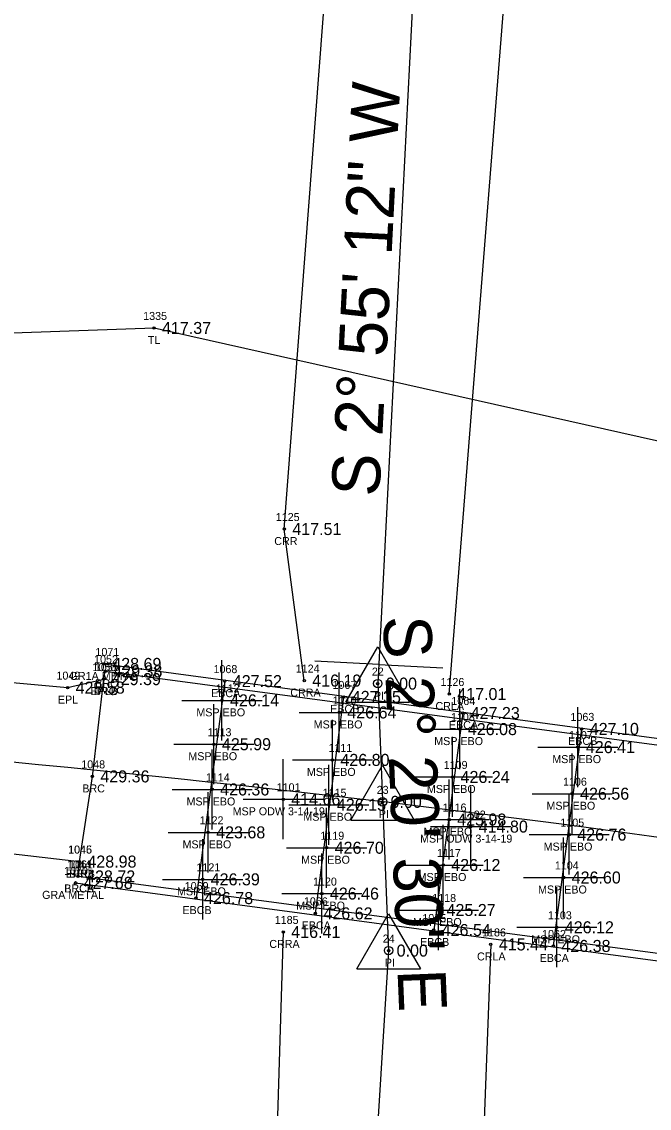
# Model space of a CAD drawing. Extents: x 1611114 to 1617038, y 769445 to 772083.
# Drawn here: x 1613882.1 to 1613960.4, y 771305 to 771440.8 of the extents above; entities that cross this region are included whole.
import ezdxf

# ---------------------------------------------------------------- set-up
doc = ezdxf.new("R2010")
doc.units = 0
for name, color, linetype in [('Default', 7, 'Continuous'), ('RD_EX_Bridge', 7, 'Continuous'), ('RD_EX_Bridge_txCode', 7, 'Continuous'), ('RD_EX_GuardRail', 7, 'Continuous'), ('RD_EX_GuardRail_txCode', 7, 'Continuous'), ('RD_EX_H2O', 7, 'Continuous'), ('RD_EX_H2O_txCode', 7, 'Continuous'), ('RD_EX_Road', 7, 'Continuous'), ('RD_EX_Road_txCode', 7, 'Continuous'), ('RD_EX_TX_Bridge_ELEV', 7, 'Continuous'), ('RD_EX_TX_GuardRail_ELEV', 7, 'Continuous'), ('RD_EX_TX_H2O_ELEV', 7, 'Continuous'), ('RD_EX_TX_Misc_ELEV', 7, 'Continuous'), ('RD_EX_TX_Road_ELEV', 7, 'Continuous'), ('RD_EX_TX_VEG_ELEV', 7, 'Continuous'), ('RD_EX_VEG', 7, 'Continuous'), ('RD_EX_VEG_txCode', 7, 'Continuous'), ('RD_HC_Cl', 7, 'Continuous'), ('RD_HC_Data', 7, 'Continuous'), ('RD_HC_Data_Tic', 7, 'Continuous'), ('RD_HC_Survey_ELEV', 7, 'Continuous'), ('RD_HC_txCode', 7, 'Continuous'), ('RD_SMD_Locator', 7, 'Continuous')]:
    doc.layers.add(name, color=color, linetype=linetype)

msp = doc.modelspace()

# ---------------------------------------------------------------- linework, layer by layer
at = {"layer": 'Default'}
for p, q in [((1613931.57, 771457.25), (1613926.51, 771358.07)), ((1613926.51, 771358.07), (1613927.87, 771324.72)), ((1613927.87, 771324.72), (1613922.18, 771233.88))]:
    msp.add_line(p, q, dxfattribs=at)
msp.add_arc((1613700.84, 769446.93), 1909.82, 80.96676, 95.06271, dxfattribs=at)
msp.add_arc((1613700.84, 769446.93), 1909.82, 80.96676, 95.06271, dxfattribs=at)
at = {"layer": 'RD_EX_Bridge'}
for p, q in [((1613907.06, 771350.98), (1613907.06, 771360.98)), ((1613921.71, 771349.47), (1613921.71, 771359.47)), ((1613907.41, 771358.38), (1613903.82, 771331.28)), ((1613936.76, 771347.39), (1613936.76, 771357.39)), ((1613902.06, 771355.98), (1613912.06, 771355.98)), ((1613906.05, 771345.5), (1613906.05, 771355.5)), ((1613918.73, 771329.37), (1613922.27, 771356.41)), ((1613916.71, 771354.47), (1613926.71, 771354.47)), ((1613937.12, 771354.4), (1613933.5, 771327.29)), ((1613951.5, 771345.14), (1613951.5, 771355.14)), ((1613920.85, 771343.54), (1613920.85, 771353.54)), ((1613931.76, 771352.39), (1613941.76, 771352.39)), ((1613935.85, 771341.41), (1613935.85, 771351.41)), ((1613948.45, 771325.3), (1613951.99, 771352.41)), ((1613901.05, 771350.5), (1613911.05, 771350.5)), ((1613946.5, 771350.14), (1613956.5, 771350.14)), ((1613905.83, 771339.85), (1613905.83, 771349.85)), ((1613950.78, 771339.32), (1613950.78, 771349.32)), ((1613915.85, 771348.54), (1613925.85, 771348.54)), ((1613920.41, 771337.94), (1613920.41, 771347.94)), ((1613930.85, 771346.41), (1613940.85, 771346.41)), ((1613935.43, 771336.09), (1613935.43, 771346.09)), ((1613900.83, 771344.85), (1613910.83, 771344.85)), ((1613905.33, 771334.49), (1613905.33, 771344.49)), ((1613945.78, 771344.32), (1613955.78, 771344.32)), ((1613950.43, 771334.21), (1613950.43, 771344.21)), ((1613915.41, 771342.94), (1613925.41, 771342.94)), ((1613920.13, 771332.57), (1613920.13, 771342.57)), ((1613930.43, 771341.09), (1613940.43, 771341.09)), ((1613900.33, 771339.49), (1613910.33, 771339.49)), ((1613934.69, 771330.41), (1613934.69, 771340.41)), ((1613945.43, 771339.21), (1613955.43, 771339.21)), ((1613904.65, 771328.62), (1613904.65, 771338.62)), ((1613949.73, 771328.85), (1613949.73, 771338.85)), ((1613915.13, 771337.57), (1613925.13, 771337.57)), ((1613919.53, 771326.84), (1613919.53, 771336.84)), ((1613929.69, 771335.41), (1613939.69, 771335.41)), ((1613934.1, 771324.79), (1613934.1, 771334.79)), ((1613944.73, 771333.85), (1613954.73, 771333.85)), ((1613899.65, 771333.62), (1613909.65, 771333.62)), ((1613948.87, 771322.63), (1613948.87, 771332.63)), ((1613914.53, 771331.84), (1613924.53, 771331.84)), ((1613929.1, 771329.79), (1613939.1, 771329.79)), ((1613943.87, 771327.63), (1613953.87, 771327.63))]:
    msp.add_line(p, q, dxfattribs=at)
msp.add_lwpolyline([(1613889.09, 771333.98), (1613889.25, 771335.84), (1613890.87, 771346.48), (1613892.3, 771358.63), (1613892.48, 771359.61), (1613966.64, 771349.7), (1613966.21, 771346.72), (1613965.11, 771336.88), (1613963.41, 771324.71), (1613963.37, 771324.1), (1613889.09, 771333.98)], dxfattribs=at)
for centre in [(1613907.06, 771355.98), (1613921.71, 771354.47), (1613936.76, 771352.39), (1613906.05, 771350.5), (1613951.5, 771350.14), (1613920.85, 771348.54), (1613935.85, 771346.41), (1613905.83, 771344.85), (1613950.78, 771344.32), (1613920.41, 771342.94), (1613935.43, 771341.09), (1613905.33, 771339.49), (1613950.43, 771339.21), (1613920.13, 771337.57), (1613934.69, 771335.41), (1613904.65, 771333.62), (1613949.73, 771333.85), (1613919.53, 771331.84), (1613934.1, 771329.79), (1613948.87, 771327.63)]:
    msp.add_circle(centre, 0.15, dxfattribs=at)
at = {"layer": 'RD_EX_GuardRail'}
for p, q in [((1613892.36, 771360.53), (1613966.88, 771350.5)), ((1613888.77, 771333.18), (1613963.37, 771323.19))]:
    msp.add_line(p, q, dxfattribs=at)
at = {"layer": 'RD_EX_H2O'}
for p, q in [((1613914.71, 771338.62), (1613914.71, 771348.62)), ((1613938.12, 771335.21), (1613938.12, 771345.21)), ((1613909.71, 771343.62), (1613919.71, 771343.62)), ((1613933.12, 771340.21), (1613943.12, 771340.21))]:
    msp.add_line(p, q, dxfattribs=at)
for points in [[(1613935.44, 771356.77), (1613943.27, 771455.38), (1613930.01, 771555.13), (1613904.31, 771653.52), (1613890.61, 771671.71), (1613879.59, 771707.51), (1613867.74, 771752.9), (1613852.65, 771773.53), (1613849.08, 771793.99), (1613835.96, 771848.52)], [(1613917.33, 771358.45), (1613914.84, 771377.38), (1613920.97, 771458.1), (1613902.34, 771553.43), (1613877.06, 771642.7), (1613869.36, 771660.93), (1613852.51, 771699.26), (1613841.87, 771743.26), (1613831.92, 771763.8), (1613826.06, 771789.11), (1613812.2, 771844.94)], [(1613914.71, 771327.05), (1613912.94, 771270.2), (1613909.29, 771229.14), (1613936.32, 771173.24), (1613961.59, 771155.78), (1613976.99, 771153.11), (1613987.89, 771138.66), (1614016.07, 771061.15), (1614064.07, 770971.34), (1614114.62, 770881.02)], [(1613940.63, 771325.49), (1613938.42, 771267.33), (1613934.3, 771235.92), (1613956.7, 771194.52), (1613973.34, 771185.91), (1613987.6, 771179.19), (1614011.07, 771155.33), (1614038.76, 771071.93), (1614097.41, 770977.46), (1614139.24, 770893.98)]]:
    msp.add_lwpolyline(points, dxfattribs=at)
for centre in [(1613914.71, 771343.62), (1613938.12, 771340.21)]:
    msp.add_circle(centre, 0.15, dxfattribs=at)
at = {"layer": 'RD_EX_Road'}
for points in [[(1613192.48, 771329.15), (1613292.05, 771338.23), (1613391, 771348.45), (1613492.61, 771357.17), (1613541.86, 771361.21), (1613591.56, 771364.71), (1613642.92, 771366.4), (1613692.81, 771367.35), (1613742.66, 771367.02), (1613792.19, 771365.04), (1613843.32, 771361.63), (1613887.78, 771357.57), (1613892.3, 771358.63)], [(1613194.6, 771309.27), (1613294.55, 771318.15), (1613393.75, 771328.31), (1613493.74, 771336.74), (1613544.27, 771340.57), (1613593.48, 771343.76), (1613642.77, 771345.54), (1613692.58, 771346.11), (1613741.71, 771345.82), (1613791.79, 771344.79), (1613840.79, 771341.46), (1613889.25, 771335.84)]]:
    msp.add_lwpolyline(points, dxfattribs=at)
at = {"layer": 'RD_EX_VEG'}
msp.add_lwpolyline([(1613190.16, 771350.86), (1613289.21, 771359.12), (1613387.94, 771369.51), (1613489.82, 771379.95), (1613503.78, 771396.75), (1613539.01, 771398.99), (1613588.71, 771402.91), (1613642.02, 771405.83), (1613690.35, 771406.29), (1613743.43, 771406.09), (1613794.76, 771402.87), (1613849.1, 771400.75), (1613898.57, 771402.5), (1614071.38, 771363.76), (1614171, 771346.54), (1614270.56, 771328.42), (1614365.98, 771308.81), (1614467.36, 771290.78), (1614565.75, 771274.12), (1614666.78, 771259.85)], dxfattribs=at)
at = {"layer": 'RD_HC_Cl'}
for p, q in [((1613931.57, 771457.25), (1613926.51, 771358.07)), ((1613926.51, 771358.07), (1613927.87, 771324.72)), ((1613927.87, 771324.72), (1613922.18, 771233.88))]:
    msp.add_line(p, q, dxfattribs=at)
msp.add_arc((1613700.84, 769446.93), 1909.82, 80.96676, 95.06271, dxfattribs=at)
at = {"layer": 'RD_HC_Data'}
for p, q in [((1613922.54, 771355.77), (1613926.51, 771362.65)), ((1613926.51, 771362.65), (1613930.48, 771355.77)), ((1613922.54, 771355.77), (1613930.48, 771355.77)), ((1613923.14, 771341.01), (1613927.11, 771347.89)), ((1613927.11, 771347.89), (1613931.08, 771341.01)), ((1613923.14, 771341.01), (1613931.08, 771341.01)), ((1613923.9, 771322.43), (1613927.87, 771329.31)), ((1613927.87, 771329.31), (1613931.84, 771322.43)), ((1613923.9, 771322.43), (1613931.84, 771322.43))]:
    msp.add_line(p, q, dxfattribs=at)
for centre in [(1613926.51, 771358.07), (1613927.11, 771343.3), (1613927.87, 771324.72)]:
    msp.add_circle(centre, 0.529, dxfattribs=at)
at = {"layer": 'RD_HC_Data_Tic'}
for q in [(1613918.64, 771360.88), (1613934.62, 771360.06)]:
    msp.add_line((1613926.63, 771360.47), q, dxfattribs=at)
at = {"layer": 'RD_SMD_Locator'}
for centre in [(1613898.57, 771402.5), (1613914.84, 771377.38), (1613892.36, 771360.53), (1613892.48, 771359.61), (1613892.3, 771358.63), (1613892.3, 771358.63), (1613907.41, 771358.38), (1613917.33, 771358.45), (1613926.51, 771358.07), (1613887.78, 771357.57), (1613935.44, 771356.77), (1613922.27, 771356.41), (1613937.12, 771354.4), (1613951.99, 771352.41), (1613890.87, 771346.48), (1613927.11, 771343.3), (1613889.25, 771335.84), (1613889.25, 771335.84), (1613889.09, 771333.98), (1613889.09, 771333.98), (1613888.77, 771333.18), (1613903.82, 771331.28), (1613918.73, 771329.37), (1613914.71, 771327.05), (1613933.5, 771327.29), (1613940.63, 771325.49), (1613927.87, 771324.72), (1613948.45, 771325.3)]:
    msp.add_circle(centre, 0.15, dxfattribs=at)

# ---------------------------------------------------------------- texts
at = {"layer": 'RD_EX_Bridge_txCode'}
for s, p in [('1052', (1613891.09, 771360.61)), ('1051', (1613891.2, 771359.63)), ('1068', (1613906, 771359.38)), ('BRC', (1613891.23, 771357.61)), ('1067', (1613920.86, 771357.41)), ('BRC', (1613891.05, 771356.63)), ('EBCA', (1613905.7, 771356.38)), ('1112', (1613906.28, 771356.98)), ('EBCB', (1613920.57, 771354.41)), ('1110', (1613920.89, 771355.47)), ('1064', (1613935.71, 771355.4)), ('MSP EBO', (1613903.86, 771353.98)), ('1108', (1613935.66, 771353.39)), ('1063', (1613950.58, 771353.41)), ('MSP EBO', (1613918.51, 771352.47)), ('EBCA', (1613935.4, 771352.4)), ('1113', (1613905.27, 771351.5)), ('MSP EBO', (1613933.57, 771350.39)), ('EBCB', (1613950.29, 771350.41)), ('1107', (1613950.4, 771351.14)), ('1111', (1613920.36, 771349.54)), ('MSP EBO', (1613902.86, 771348.5)), ('MSP EBO', (1613948.31, 771348.14)), ('1048', (1613889.49, 771347.48)), ('MSP EBO', (1613917.66, 771346.54)), ('1109', (1613934.75, 771347.41)), ('1114', (1613905.05, 771345.85)), ('1106', (1613949.65, 771345.32)), ('BRC', (1613889.62, 771344.48)), ('1115', (1613919.63, 771343.94)), ('MSP EBO', (1613932.65, 771344.41)), ('MSP EBO', (1613902.63, 771342.85)), ('MSP EBO', (1613947.58, 771342.32)), ('MSP EBO', (1613917.22, 771340.94)), ('1116', (1613934.62, 771342.09)), ('1122', (1613904.27, 771340.49)), ('1105', (1613949.32, 771340.21)), ('1119', (1613919.35, 771338.57)), ('MSP EBO', (1613932.23, 771339.09)), ('1045', (1613887.86, 771336.84)), ('MSP EBO', (1613902.13, 771337.49)), ('MSP EBO', (1613947.23, 771337.21)), ('MSP EBO', (1613916.94, 771335.57)), ('1117', (1613933.91, 771336.41)), ('1044', (1613887.71, 771334.98)), ('1061', (1613887.97, 771334.98)), ('1121', (1613903.87, 771334.62)), ('1104', (1613948.63, 771334.85)), ('BRC', (1613887.99, 771333.84)), ('1120', (1613918.43, 771332.84)), ('MSP EBO', (1613931.49, 771333.41)), ('BRCA', (1613887.35, 771331.98)), ('BRCB', (1613887.37, 771331.98)), ('MSP EBO', (1613901.45, 771331.62)), ('1069', (1613902.41, 771332.28)), ('MSP EBO', (1613946.53, 771331.85)), ('1066', (1613917.29, 771330.37)), ('1118', (1613933.32, 771330.79)), ('EBCB', (1613902.12, 771329.28)), ('MSP EBO', (1613916.33, 771329.84)), ('1103', (1613947.77, 771328.63)), ('EBCA', (1613917.01, 771327.37)), ('MSP EBO', (1613930.91, 771327.79)), ('1065', (1613932.09, 771328.29)), ('1062', (1613947.04, 771326.3)), ('EBCB', (1613931.8, 771325.29)), ('MSP EBO', (1613945.68, 771325.63)), ('EBCA', (1613946.73, 771323.3))]:
    msp.add_text(s, height=1, dxfattribs=at).set_placement(p)
at = {"layer": 'RD_EX_GuardRail_txCode'}
for s, p in [('1071', (1613891.26, 771361.53)), ('GR1A METAL', (1613888.03, 771358.53)), ('1070', (1613887.34, 771334.18)), ('GRA METAL', (1613884.6, 771331.18))]:
    msp.add_text(s, height=1, dxfattribs=at).set_placement(p)
at = {"layer": 'RD_EX_H2O_txCode'}
for s, p in [('1125', (1613913.78, 771378.38)), ('CRR', (1613913.59, 771375.38)), ('1124', (1613916.27, 771359.45)), ('1126', (1613934.35, 771357.77)), ('CRRA', (1613915.59, 771356.45)), ('CRLA', (1613933.72, 771354.77)), ('1101', (1613913.89, 771344.62)), ('MSP ODW 3-14-19', (1613908.39, 771341.62)), ('1102', (1613937.02, 771341.21)), ('MSP ODW 3-14-19', (1613931.8, 771338.21)), ('1185', (1613913.65, 771328.05)), ('1186', (1613939.54, 771326.49)), ('CRRA', (1613912.97, 771325.05)), ('CRLA', (1613938.91, 771323.49))]:
    msp.add_text(s, height=1, dxfattribs=at).set_placement(p)
at = {"layer": 'RD_EX_Road_txCode'}
for s, p in [('1049', (1613886.39, 771358.57)), ('1050', (1613890.88, 771359.63)), ('EPLB', (1613890.63, 771356.63)), ('EPL', (1613886.57, 771355.57)), ('1046', (1613887.84, 771336.84)), ('EPRB', (1613887.54, 771333.84))]:
    msp.add_text(s, height=1, dxfattribs=at).set_placement(p)
at = {"layer": 'RD_EX_TX_Bridge_ELEV'}
for s, p in [('429.38', (1613893.48, 771358.86)), ('429.39', (1613893.3, 771357.88)), ('427.52', (1613908.41, 771357.63)), ('427.35', (1613923.27, 771355.66)), ('427.23', (1613938.12, 771353.65)), ('427.10', (1613952.99, 771351.66)), ('429.36', (1613891.87, 771345.73)), ('428.98', (1613890.25, 771335.09)), ('428.72', (1613890.09, 771333.23)), ('428.72', (1613890.09, 771333.23)), ('426.78', (1613904.82, 771330.53)), ('426.62', (1613919.73, 771328.62)), ('426.54', (1613934.5, 771326.54)), ('426.38', (1613949.45, 771324.55))]:
    msp.add_text(s, height=1.5, dxfattribs=at).set_placement(p)
at = {"layer": 'RD_EX_TX_GuardRail_ELEV'}
for s, p in [('428.69', (1613893.36, 771359.78)), ('427.68', (1613889.77, 771332.43))]:
    msp.add_text(s, height=1.5, dxfattribs=at).set_placement(p)
at = {"layer": 'RD_EX_TX_H2O_ELEV'}
for s, p in [('417.51', (1613915.84, 771376.63)), ('416.19', (1613918.33, 771357.7)), ('417.01', (1613936.44, 771356.02)), ('416.41', (1613915.71, 771326.3)), ('415.44', (1613941.63, 771324.74))]:
    msp.add_text(s, height=1.5, dxfattribs=at).set_placement(p)
at = {"layer": 'RD_EX_TX_Misc_ELEV'}
for s, p in [('426.14', (1613908.06, 771355.23)), ('426.64', (1613922.71, 771353.72)), ('426.08', (1613937.76, 771351.64)), ('425.99', (1613907.05, 771349.75)), ('426.41', (1613952.5, 771349.39)), ('426.80', (1613921.85, 771347.79)), ('426.24', (1613936.85, 771345.66)), ('426.36', (1613906.83, 771344.1)), ('426.56', (1613951.78, 771343.57)), ('414.66', (1613915.71, 771342.87)), ('426.15', (1613921.41, 771342.19)), ('425.98', (1613936.43, 771340.34)), ('414.80', (1613939.12, 771339.46)), ('423.68', (1613906.33, 771338.74)), ('426.76', (1613951.43, 771338.46)), ('426.70', (1613921.13, 771336.82)), ('426.12', (1613935.69, 771334.66)), ('426.39', (1613905.65, 771332.87)), ('426.60', (1613950.73, 771333.1)), ('426.46', (1613920.53, 771331.09)), ('425.27', (1613935.1, 771329.04)), ('426.12', (1613949.87, 771326.88))]:
    msp.add_text(s, height=1.5, dxfattribs=at).set_placement(p)
at = {"layer": 'RD_EX_TX_Road_ELEV'}
for s, p in [('429.58', (1613888.78, 771356.82)), ('429.39', (1613893.3, 771357.88)), ('428.98', (1613890.25, 771335.09))]:
    msp.add_text(s, height=1.5, dxfattribs=at).set_placement(p)
at = {"layer": 'RD_EX_TX_VEG_ELEV'}
msp.add_text('417.37', height=1.5, dxfattribs=at).set_placement((1613899.57, 771401.75))
at = {"layer": 'RD_EX_VEG_txCode'}
for s, p in [('1335', (1613897.22, 771403.5)), ('TL', (1613897.79, 771400.5))]:
    msp.add_text(s, height=1, dxfattribs=at).set_placement(p)
at = {"layer": 'RD_HC_Data'}
for s, rotation, p in [('S 2%%d 55\' 12" W', 87.08, (1613926.7, 771381.36)), ('S 2%%d 20\' 30" E', 272.3416, (1613927.17, 771366.45))]:
    msp.add_text(s, height=6, rotation=rotation, dxfattribs=at).set_placement(p)
at = {"layer": 'RD_HC_Survey_ELEV'}
for p in [(1613927.51, 771357.32), (1613928.11, 771342.55), (1613928.87, 771323.97)]:
    msp.add_text('0.00', height=1.5, dxfattribs=at).set_placement(p)
at = {"layer": 'RD_HC_txCode'}
for s, p in [('22', (1613925.78, 771359.07)), ('PI', (1613926.04, 771356.07)), ('23', (1613926.38, 771344.3)), ('PI', (1613926.64, 771341.3)), ('24', (1613927.14, 771325.72)), ('PI', (1613927.4, 771322.72))]:
    msp.add_text(s, height=1, dxfattribs=at).set_placement(p)

doc.saveas('drawing.dxf')
